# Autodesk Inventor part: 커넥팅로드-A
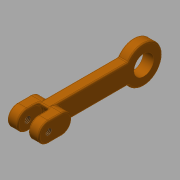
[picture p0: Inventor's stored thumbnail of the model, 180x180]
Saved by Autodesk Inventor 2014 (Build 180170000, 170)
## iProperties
Created: 2018-01
Part Number: 커넥팅로드-A
Material: 알루미늄 6061
Document SubType Name: Modeling
Designer: mduedu
Density: 2.71 g/cm^3
Appearance: 주황색
Mass: 5.11804 g
Surface Area: 16.3537 cm^2
Volume: 1.88857 cm^3
Author: mduedu
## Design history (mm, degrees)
sketch "스케치1"
  geometry: L1 (0, 0)-(0, 40); L2 (3.75, 40)-(3.75, 5.911); L3 (-3.75, 40)-(-3.75, 5.911); A1 r 7 centre (0, 0) between (3.75, 5.911) and (-3.75, 5.911); A2 r 3.75 centre (0, 40) between (3.75, 40) and (-3.75, 40); 1 further point
  constraints: 6 end point, 4 point on circle, 2 centre point, 2 coincident, 2 parallel, 2 tangent, 1 vertical
  dimensions: "d1" = 40 distance of L1.start L1.end; "d2" = 7.5 diameter of A2; "d3" = 14 diameter of A1
extrude "돌출1" new body sketch "스케치1" stored distance "d4" = 4; taper "d5" = 0 deg
sketch "스케치2"
  geometry: L1 (-3.75, 40)-(-3.75, 35); L2 (3.75, 40)-(3.75, 35); A1 r 3.75 centre (0, 40) between (3.75, 40) and (-3.75, 40) reference; A2 r 3.75 centre (0, 40) between (3.75, 40) and (-3.75, 40); A3 r 3.75 centre (0, 35) between (-3.75, 35) and (3.75, 35); 1 further point
  constraints: 4 end point, 4 point on circle, 2 centre point, 2 tangent, 1 coincident, 1 equal radius, 1 point on line, 1 vertical alignment
  dimensions: "d6" = 5 distance of A3.centre A1.centre
extrude "돌출2" join sketch "스케치2" stored distance "d7" = 12; taper "d8" = 0 deg
sketch "스케치3"
  geometry: L1 (3.75, 40)-(3.75, 38); L2 (-3.75, 40)-(-3.75, 38); A1 r 3.75 centre (0, 40) between (3.75, 40) and (-3.75, 40) reference; A2 r 3.75 centre (0, 40) between (3.75, 40) and (-3.75, 40); A3 r 3.75 centre (0, 38) between (-3.75, 38) and (3.75, 38); 1 further point
  constraints: 4 end point, 4 point on circle, 3 tangent, 2 centre point, 1 coincident, 1 equal radius, 1 parallel, 1 point on line
  dimensions: "d9" = 2 distance of A3.centre A1.centre
extrude "돌출3" cut sketch "스케치3" stored distance "d10" = 4; taper "d11" = 0 deg
fillet "모깎기5" dims "d16" = 0.5
fillet "모깎기6" dims "d17" = 0.5
fillet "모깎기7" dims "d18" = 0.5
fillet "모깎기8" dims "d19" = 0.5
hole "구멍1" diameter "d22" = 7.5; stored, may be unused: countersink angle "d26" = 90 deg, drill point angle "d28" = 118 deg; dims "d20" = 10, "d21" = 10, "d23" = 6, "d24" = 4, "d25" = 2, "d27" = 8
sketch "스케치4"
  geometry: A1 r 3.75 centre (40, 0) between (40, -3.75) and (40, 3.75) reference; 2 further points
  constraints: 1 coincident
sketch "스케치5"
  geometry: 1 further point
  constraints: 1 other
hole "구멍2" sketch "스케치5" at (40, 0) diameter "d29" = 2.459; stored, may be unused: countersink angle "d33" = 90 deg, drill point angle "d35" = 0 deg; dims "d30" = 6, "d31" = 4, "d32" = 2, "d34" = 8
sketch "스케치6"
  geometry: 1 further point
  constraints: 1 other
hole "구멍4" sketch "스케치6" at (-40, 0) diameter "d36" = 2.459; stored, may be unused: countersink angle "d40" = 90 deg, drill point angle "d42" = 0 deg; dims "d37" = 6, "d38" = 4, "d39" = 2, "d41" = 8
node "솔리드1"
